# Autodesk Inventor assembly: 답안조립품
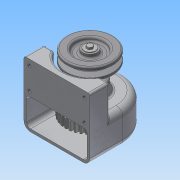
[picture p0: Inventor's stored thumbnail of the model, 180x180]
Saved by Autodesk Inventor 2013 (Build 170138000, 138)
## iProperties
Created: 2015-02
Part Number: 답안조립품
Document SubType Name: Assembly
Designer: Administrator
Author: Administrator
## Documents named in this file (14)
- C:\Documents and Settings\Administrator\바탕 화면\450214V1014\답안조립품.iam
- C:\Documents and Settings\Administrator\바탕 화면\450214V1014\1-본체.ipt
- C:\Documents and Settings\Administrator\바탕 화면\450214V1014\베어링 6001.ipt
- C:\Documents and Settings\Administrator\바탕 화면\450214V1014\축.ipt
- C:\Documents and Settings\Administrator\바탕 화면\450214V1014\키5x5.ipt
- C:\Documents and Settings\Administrator\바탕 화면\450214V1014\키4x4.ipt
- C:\Documents and Settings\Administrator\바탕 화면\450214V1014\스퍼기어.ipt
- C:\Documents and Settings\Administrator\바탕 화면\450214V1014\축커버.ipt
- C:\Documents and Settings\Administrator\바탕 화면\450214V1014\오일실.ipt
- C:\Documents and Settings\Administrator\바탕 화면\450214V1014\M3x0.5.ipt
- C:\Documents and Settings\Administrator\바탕 화면\450214V1014\4-V-벨트풀리.ipt
- C:\Documents and Settings\Administrator\바탕 화면\450214V1014\M5x0.8.ipt
- M5x0.8.ipt
- C:\Documents and Settings\Administrator\바탕 화면\450214V1014\와샤.ipt
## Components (7 placed, 4 different names)
1. 1-본체:1 — 각도:5
2. 4-V-벨트풀리:1 — 각도:4
3. M5x0.8:1 — 각도:5
4. M3x0.5:1
5. M3x0.5:2
6. M3x0.5:3
7. M3x0.5:4
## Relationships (2: Angle 2)
- 각도:4 [Angle]: 4-V-벨트풀리:1
- 각도:5 [Angle]: 1-본체:1 ↔ M5x0.8:1
